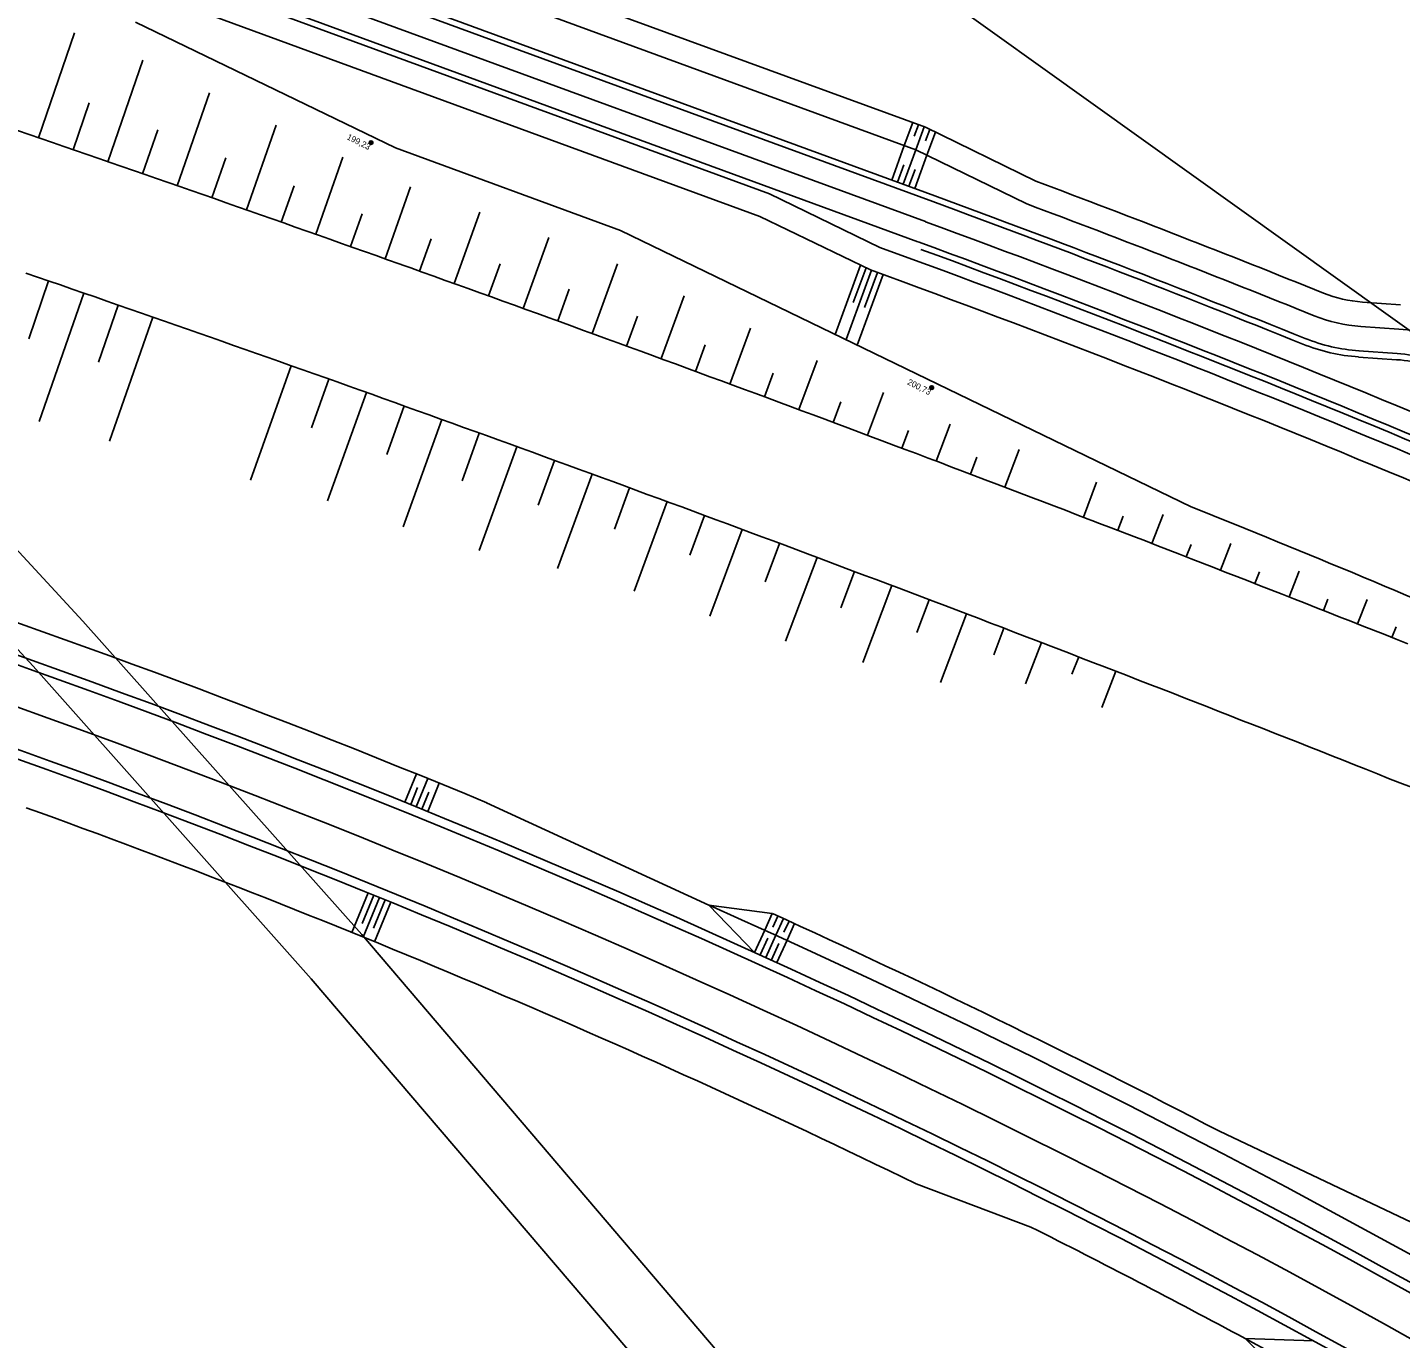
# Model space of a CAD drawing. Extents: x -551750 to -547457, y -1150683 to -1148508.
# Drawn here: x -550804.2 to -550691.9, y -1148887.3 to -1148780.1 of the extents above; entities that cross this region are included whole.
import ezdxf

# ---------------------------------------------------------------- set-up
doc = ezdxf.new("R2010")
doc.units = 0
for name, color, linetype in [('D02_ZaplUzemi20Vody', 7, 'Continuous'), ('D03_ZaplUzemi100Vody', 7, 'Continuous'), ('SO221815_VYSKOPIS', 7, 'Continuous'), ('u_ochranne_pasmo_CD', 7, 'Continuous'), ('u_trat navrh', 7, 'Continuous')]:
    doc.layers.add(name, color=color, linetype=linetype)

# ---------------------------------------------------------------- blocks, each defined once
blk = doc.blocks.new('SO221824_VYSKOPIS')
at = {"layer": 'SO221815_VYSKOPIS'}
for p, q in [((0.12, -0.09), (-0.12, 0.09)), ((0.09, 0.12), (-0.09, -0.12)), ((0.09, 0.12), (0, 0)), ((0, 0), (0.12, -0.09))]:
    blk.add_line(p, q, dxfattribs=at)
blk.add_lwpolyline([(-0.09, -0.12), (0, 0), (-0.12, 0.09)], dxfattribs=at)
blk.add_circle((0, 0), 0.15, dxfattribs=at)
for start, end in [(145.362, 235.1538), (325.362, 55.1538)]:
    blk.add_arc((0, 0), 0.15, start, end, dxfattribs=at)

msp = doc.modelspace()

# ---------------------------------------------------------------- linework, layer by layer
at = {"layer": 'D02_ZaplUzemi20Vody'}
msp.add_lwpolyline([(-550912.3, -1148731.6), (-550896.22, -1148741.39), (-550850.59, -1148781.5), (-550803.72, -1148832.3), (-550780.99, -1148857.84), (-550750.48, -1148893.58), (-550736.72, -1148911.7), (-550729.53, -1148926.8), (-550718.48, -1148952.6), (-550708.97, -1148984.08), (-550705.33, -1149008.81), (-550704.61, -1149029.83), (-550710.53, -1149089.8)], dxfattribs=at)
at = {"layer": 'D03_ZaplUzemi100Vody'}
msp.add_lwpolyline([(-550923.25, -1148724.56), (-550910.54, -1148726.8), (-550892.6, -1148737.27), (-550846.76, -1148777.57), (-550799.66, -1148828.62), (-550776.86, -1148854.24), (-550746.22, -1148890.14), (-550732.01, -1148908.84), (-550724.54, -1148924.55), (-550713.33, -1148950.72), (-550703.61, -1148982.89), (-550699.87, -1149008.32), (-550699.12, -1149030.01), (-550705.1, -1149090.59)], dxfattribs=at)
at = {"layer": 'u_ochranne_pasmo_CD'}
msp.add_lwpolyline([(-551192.01, -1148633.8), (-551157.64, -1148630.18), (-551128.55, -1148628.56), (-551093.1, -1148628.4), (-551065.82, -1148629.19), (-551032.97, -1148632.59), (-551007.77, -1148636.86), (-550975.72, -1148645.44), (-550950.32, -1148653.02), (-550933.85, -1148658.78), (-550881.95, -1148680.12), (-550842.85, -1148701.03), (-550797.65, -1148728.66), (-550648.81, -1148835.14), (-550577.65, -1148890.43), (-550478.43, -1148960.24), (-550334.99, -1149075.5), (-550242.86, -1149142.59), (-550154.88, -1149215.07), (-550068.29, -1149277.57)], dxfattribs=at)
at = {"layer": 'u_trat navrh'}
for p, q in [((-550730.77, -1148788.22), (-550845.88, -1148746.02)), ((-550731.56, -1148790.07), (-550846.57, -1148747.9)), ((-550730, -1148793.83), (-550847.6, -1148750.72)), ((-550730.17, -1148794.3), (-550847.77, -1148751.19)), ((-550730.77, -1148795.94), (-550848.38, -1148752.83)), ((-550743.53, -1148793.66), (-550849.15, -1148754.94)), ((-550731.38, -1148797.59), (-550848.98, -1148754.47)), ((-550744.31, -1148795.51), (-550849.84, -1148756.82)), ((-550795.36, -1148779.62), (-550774.11, -1148789.91)), ((-550803.29, -1148789.08), (-550800.36, -1148780.51)), ((-550797.62, -1148791.04), (-550794.76, -1148782.75)), ((-550791.95, -1148793), (-550789.3, -1148785.4)), ((-550800.45, -1148790.06), (-550799.14, -1148786.23)), ((-550732.5, -1148789.72), (-550731.81, -1148787.84)), ((-550794.78, -1148792.02), (-550793.54, -1148788.44)), ((-550786.28, -1148794.98), (-550783.85, -1148788.04)), ((-550731.68, -1148788.95), (-550731.34, -1148788.02)), ((-550731.56, -1148790.07), (-550730.87, -1148788.19)), ((-550721.74, -1148792.63), (-550730.77, -1148788.22)), ((-550730.76, -1148789.34), (-550730.42, -1148788.4)), ((-550730.66, -1148790.51), (-550729.96, -1148788.62)), ((-550755.7, -1148796.66), (-550774.11, -1148789.91)), ((-550733.53, -1148792.54), (-550732.5, -1148789.72)), ((-550732.59, -1148792.88), (-550731.56, -1148790.07)), ((-550722.53, -1148794.47), (-550731.56, -1148790.07)), ((-550789.11, -1148793.99), (-550787.97, -1148790.72)), ((-550780.62, -1148796.97), (-550778.4, -1148790.68)), ((-550733.06, -1148792.71), (-550732.55, -1148791.3)), ((-550731.65, -1148793.23), (-550730.66, -1148790.51)), ((-550732.12, -1148793.05), (-550731.62, -1148791.67)), ((-550783.45, -1148795.98), (-550782.4, -1148793)), ((-550774.96, -1148798.98), (-550772.87, -1148793.09)), ((-550743.53, -1148793.66), (-550734.49, -1148798.05)), ((-550777.79, -1148797.98), (-550776.84, -1148795.29)), ((-550769.31, -1148801), (-550767.22, -1148795.16)), ((-550744.31, -1148795.51), (-550735.27, -1148799.89)), ((-550755.7, -1148796.66), (-550709.03, -1148819.26)), ((-550772.14, -1148799.99), (-550771.19, -1148797.35)), ((-550763.67, -1148803.04), (-550761.57, -1148797.23)), ((-550731.89, -1148799), (-550734.49, -1148798.05)), ((-550766.49, -1148802.02), (-550765.55, -1148799.4)), ((-550758.02, -1148805.08), (-550755.95, -1148799.38)), ((-550736.08, -1148799.49), (-550738.16, -1148805.16)), ((-550735.17, -1148799.92), (-550737.25, -1148805.59)), ((-550735.63, -1148799.71), (-550736.67, -1148802.54)), ((-550734.23, -1148800.27), (-550736.35, -1148806.03)), ((-550734.7, -1148800.1), (-550735.75, -1148802.95)), ((-550732.58, -1148800.87), (-550735.27, -1148799.89)), ((-550802.47, -1148800.79), (-550804.09, -1148805.51)), ((-550760.84, -1148804.06), (-550759.9, -1148801.45)), ((-550799.6, -1148801.78), (-550803.23, -1148812.27)), ((-550752.39, -1148807.14), (-550750.51, -1148802.02)), ((-550695.04, -1148802.52), (-550691.92, -1148802.74)), ((-550796.77, -1148802.76), (-550798.39, -1148807.42)), ((-550755.21, -1148806.11), (-550754.32, -1148803.68)), ((-550793.94, -1148803.74), (-550797.48, -1148813.89)), ((-550746.76, -1148809.22), (-550745.07, -1148804.65)), ((-550695.18, -1148804.51), (-550692.06, -1148804.73)), ((-550749.57, -1148808.18), (-550748.77, -1148806)), ((-550695.35, -1148807.01), (-550692.24, -1148807.23)), ((-550695.32, -1148806.51), (-550692.2, -1148806.73)), ((-550782.64, -1148807.72), (-550785.95, -1148817.08)), ((-550741.13, -1148811.31), (-550739.63, -1148807.29)), ((-550779.56, -1148808.81), (-550780.98, -1148812.81)), ((-550743.94, -1148810.26), (-550743.23, -1148808.33)), ((-550776.48, -1148809.91), (-550779.65, -1148818.78)), ((-550735.51, -1148813.41), (-550734.2, -1148809.92)), ((-550773.4, -1148811.01), (-550774.82, -1148814.98)), ((-550738.32, -1148812.35), (-550737.69, -1148810.67)), ((-550770.32, -1148812.12), (-550773.48, -1148820.89)), ((-550729.89, -1148815.52), (-550728.75, -1148812.5)), ((-550767.25, -1148813.23), (-550768.66, -1148817.14)), ((-550732.7, -1148814.46), (-550732.15, -1148813.01)), ((-550764.17, -1148814.34), (-550767.25, -1148822.82)), ((-550724.28, -1148817.65), (-550723.11, -1148814.57)), ((-550761.1, -1148815.46), (-550762.43, -1148819.11)), ((-550727.08, -1148816.58), (-550726.57, -1148815.21)), ((-550758.03, -1148816.58), (-550760.86, -1148824.3)), ((-550754.96, -1148817.7), (-550756.2, -1148821.08)), ((-550717.86, -1148820.1), (-550716.77, -1148817.25)), ((-550751.89, -1148818.83), (-550754.59, -1148826.15)), ((-550748.83, -1148819.97), (-550750.03, -1148823.2)), ((-550715.05, -1148821.18), (-550714.6, -1148820.01)), ((-550712.25, -1148822.26), (-550711.33, -1148819.89)), ((-550745.76, -1148821.11), (-550748.4, -1148828.21)), ((-550742.7, -1148822.25), (-550743.87, -1148825.39)), ((-550709.44, -1148823.35), (-550709.05, -1148822.35)), ((-550706.64, -1148824.44), (-550705.79, -1148822.25)), ((-550739.63, -1148823.39), (-550742.2, -1148830.23)), ((-550736.57, -1148824.54), (-550737.69, -1148827.51)), ((-550703.84, -1148825.53), (-550703.46, -1148824.57)), ((-550701.03, -1148826.63), (-550700.21, -1148824.53)), ((-550733.51, -1148825.7), (-550735.89, -1148831.99)), ((-550730.46, -1148826.85), (-550731.47, -1148829.54)), ((-550698.23, -1148827.73), (-550697.87, -1148826.8)), ((-550695.44, -1148828.83), (-550694.65, -1148826.84)), ((-550727.4, -1148828.02), (-550729.54, -1148833.63)), ((-550724.35, -1148829.18), (-550725.18, -1148831.35)), ((-550692.64, -1148829.94), (-550692.29, -1148829.07)), ((-550721.29, -1148830.35), (-550722.6, -1148833.74)), ((-550718.24, -1148831.53), (-550718.79, -1148832.94)), ((-550715.21, -1148832.7), (-550716.35, -1148835.66)), ((-550773.33, -1148843.41), (-550772.39, -1148841.09)), ((-550772.4, -1148843.79), (-550771.46, -1148841.47)), ((-550771.47, -1148844.17), (-550770.53, -1148841.85)), ((-550772.86, -1148843.6), (-550772.3, -1148842.21)), ((-550771.94, -1148843.98), (-550771.37, -1148842.59)), ((-550766.65, -1148843.45), (-550748.47, -1148851.82)), ((-550776.34, -1148850.82), (-550777.66, -1148854.07)), ((-550775.88, -1148851.01), (-550776.82, -1148853.33)), ((-550775.42, -1148851.2), (-550776.74, -1148854.44)), ((-550774.95, -1148851.39), (-550775.9, -1148853.7)), ((-550774.49, -1148851.58), (-550775.81, -1148854.82)), ((-550743.29, -1148852.51), (-550748.47, -1148851.82)), ((-550744.74, -1148855.69), (-550748.47, -1148851.82)), ((-550743.91, -1148853.87), (-550743.29, -1148852.51)), ((-550743.25, -1148853.63), (-550742.83, -1148852.72)), ((-550743, -1148854.29), (-550742.38, -1148852.92)), ((-550743.91, -1148853.87), (-550744.74, -1148855.69)), ((-550742.34, -1148854.04), (-550741.92, -1148853.13)), ((-550742.09, -1148854.7), (-550741.47, -1148853.34)), ((-550743.66, -1148854.54), (-550744.28, -1148855.9)), ((-550743, -1148854.29), (-550743.83, -1148856.11)), ((-550742.75, -1148854.95), (-550743.37, -1148856.31)), ((-550742.09, -1148854.7), (-550742.92, -1148856.52)), ((-550706.73, -1148870.31), (-550688.66, -1148878.9)), ((-550731.54, -1148874.61), (-550722.14, -1148878.15)), ((-550699.04, -1148887.45), (-550704.63, -1148887.26)), ((-550700.96, -1148890.96), (-550704.63, -1148887.26))]:
    msp.add_line(p, q, dxfattribs=at)
for points in [[(-550805, -1148788.5), (-550804.05, -1148788.82), (-550803.1, -1148789.15), (-550802.16, -1148789.47), (-550801.21, -1148789.8), (-550800.26, -1148790.12), (-550799.32, -1148790.45), (-550798.37, -1148790.78), (-550797.42, -1148791.1), (-550796.48, -1148791.43), (-550795.53, -1148791.76), (-550794.58, -1148792.09), (-550793.64, -1148792.41), (-550792.69, -1148792.74), (-550791.75, -1148793.07), (-550790.8, -1148793.4), (-550789.86, -1148793.73), (-550788.91, -1148794.06), (-550787.96, -1148794.39), (-550787.02, -1148794.72), (-550786.07, -1148795.05), (-550785.13, -1148795.39), (-550784.19, -1148795.72), (-550783.24, -1148796.05), (-550782.3, -1148796.38), (-550781.35, -1148796.72), (-550780.41, -1148797.05), (-550779.46, -1148797.38), (-550778.52, -1148797.72), (-550777.58, -1148798.05), (-550776.63, -1148798.39), (-550775.69, -1148798.72), (-550774.75, -1148799.06), (-550773.8, -1148799.4), (-550773.43, -1148799.53), (-550772.86, -1148799.73), (-550771.92, -1148800.07), (-550770.97, -1148800.41), (-550770.03, -1148800.74), (-550769.09, -1148801.08), (-550768.15, -1148801.42), (-550767.2, -1148801.76), (-550766.26, -1148802.1), (-550765.32, -1148802.44), (-550764.38, -1148802.78), (-550763.44, -1148803.12), (-550762.49, -1148803.46), (-550761.55, -1148803.8), (-550760.61, -1148804.14), (-550759.67, -1148804.48), (-550758.73, -1148804.83), (-550757.79, -1148805.17), (-550756.85, -1148805.51), (-550755.91, -1148805.86), (-550754.97, -1148806.2), (-550754.03, -1148806.54), (-550753.09, -1148806.89), (-550752.15, -1148807.23), (-550751.21, -1148807.58), (-550750.27, -1148807.92), (-550749.33, -1148808.27), (-550748.39, -1148808.62), (-550747.45, -1148808.96), (-550746.51, -1148809.31), (-550745.57, -1148809.66), (-550744.63, -1148810), (-550743.69, -1148810.35), (-550742.75, -1148810.7), (-550741.81, -1148811.05), (-550740.88, -1148811.4), (-550739.94, -1148811.75), (-550739, -1148812.1), (-550738.06, -1148812.45), (-550737.12, -1148812.8), (-550736.19, -1148813.15), (-550735.25, -1148813.5), (-550734.31, -1148813.86), (-550733.37, -1148814.21), (-550732.44, -1148814.56), (-550731.5, -1148814.91), (-550730.56, -1148815.27), (-550729.62, -1148815.62), (-550728.69, -1148815.98), (-550727.75, -1148816.33), (-550726.82, -1148816.69), (-550725.88, -1148817.04), (-550724.94, -1148817.4), (-550724.01, -1148817.75), (-550723.07, -1148818.11), (-550722.14, -1148818.47), (-550721.2, -1148818.82), (-550720.27, -1148819.18), (-550719.33, -1148819.54), (-550718.39, -1148819.9), (-550717.46, -1148820.26), (-550717.16, -1148820.37), (-550716.53, -1148820.61), (-550715.59, -1148820.97), (-550714.66, -1148821.33), (-550713.72, -1148821.69), (-550712.79, -1148822.05), (-550711.85, -1148822.42), (-550710.92, -1148822.78), (-550709.99, -1148823.14), (-550709.05, -1148823.5), (-550708.12, -1148823.86), (-550707.19, -1148824.23), (-550706.25, -1148824.59), (-550705.32, -1148824.95), (-550704.39, -1148825.32), (-550703.45, -1148825.68), (-550702.52, -1148826.05), (-550701.59, -1148826.41), (-550700.66, -1148826.78), (-550699.72, -1148827.14), (-550698.79, -1148827.51), (-550697.86, -1148827.87), (-550696.93, -1148828.24), (-550696, -1148828.61), (-550695.07, -1148828.98), (-550694.13, -1148829.34), (-550693.2, -1148829.71), (-550692.27, -1148830.08), (-550691.34, -1148830.45)], [(-550804.32, -1148800.15), (-550803.38, -1148800.47), (-550802.43, -1148800.8), (-550801.49, -1148801.12), (-550800.55, -1148801.45), (-550799.6, -1148801.78), (-550798.66, -1148802.1), (-550797.71, -1148802.43), (-550796.77, -1148802.76), (-550795.83, -1148803.09), (-550794.88, -1148803.42), (-550793.94, -1148803.74), (-550793, -1148804.07), (-550792.06, -1148804.4), (-550791.11, -1148804.73), (-550790.17, -1148805.06), (-550789.23, -1148805.39), (-550788.29, -1148805.72), (-550787.34, -1148806.06), (-550786.4, -1148806.39), (-550785.46, -1148806.72), (-550784.52, -1148807.05), (-550783.58, -1148807.38), (-550782.63, -1148807.72), (-550781.69, -1148808.05), (-550780.75, -1148808.39), (-550779.81, -1148808.72), (-550778.87, -1148809.05), (-550777.93, -1148809.39), (-550776.99, -1148809.73), (-550776.92, -1148809.75), (-550776.05, -1148810.06), (-550775.11, -1148810.4), (-550774.17, -1148810.73), (-550773.23, -1148811.07), (-550772.29, -1148811.41), (-550771.35, -1148811.75), (-550770.41, -1148812.08), (-550769.47, -1148812.42), (-550768.53, -1148812.76), (-550767.59, -1148813.1), (-550766.65, -1148813.44), (-550765.71, -1148813.78), (-550764.77, -1148814.12), (-550763.83, -1148814.46), (-550762.89, -1148814.8), (-550761.96, -1148815.14), (-550761.02, -1148815.49), (-550760.08, -1148815.83), (-550759.14, -1148816.17), (-550758.2, -1148816.51), (-550757.27, -1148816.86), (-550756.33, -1148817.2), (-550755.39, -1148817.55), (-550754.45, -1148817.89), (-550753.52, -1148818.24), (-550752.58, -1148818.58), (-550751.64, -1148818.93), (-550750.7, -1148819.27), (-550749.77, -1148819.62), (-550748.83, -1148819.97), (-550747.89, -1148820.31), (-550746.96, -1148820.66), (-550746.02, -1148821.01), (-550745.09, -1148821.36), (-550744.15, -1148821.7), (-550743.21, -1148822.05), (-550742.28, -1148822.4), (-550741.34, -1148822.75), (-550740.41, -1148823.1), (-550739.47, -1148823.45), (-550738.54, -1148823.8), (-550737.6, -1148824.16), (-550736.67, -1148824.51), (-550735.73, -1148824.86), (-550734.8, -1148825.21), (-550733.86, -1148825.56), (-550732.93, -1148825.92), (-550732, -1148826.27), (-550731.06, -1148826.63), (-550730.13, -1148826.98), (-550729.19, -1148827.33), (-550728.26, -1148827.69), (-550727.33, -1148828.04), (-550726.39, -1148828.4), (-550725.46, -1148828.76), (-550724.53, -1148829.11), (-550723.6, -1148829.47), (-550722.66, -1148829.83), (-550721.73, -1148830.18), (-550720.8, -1148830.54), (-550720.73, -1148830.57), (-550719.87, -1148830.9), (-550718.93, -1148831.26), (-550718, -1148831.62), (-550717.07, -1148831.98), (-550716.14, -1148832.34), (-550715.21, -1148832.7), (-550714.28, -1148833.06), (-550713.34, -1148833.42), (-550712.41, -1148833.78), (-550711.48, -1148834.14), (-550710.55, -1148834.5), (-550709.62, -1148834.87), (-550708.69, -1148835.23), (-550707.76, -1148835.59), (-550706.83, -1148835.96), (-550705.9, -1148836.32), (-550704.97, -1148836.69), (-550704.04, -1148837.05), (-550703.11, -1148837.42), (-550702.18, -1148837.78), (-550701.25, -1148838.15), (-550700.32, -1148838.51), (-550699.39, -1148838.88), (-550698.47, -1148839.25), (-550697.54, -1148839.61), (-550696.61, -1148839.98), (-550695.68, -1148840.35), (-550694.75, -1148840.72), (-550693.82, -1148841.09), (-550692.9, -1148841.46), (-550691.97, -1148841.82), (-550691.04, -1148842.19)]]:
    msp.add_lwpolyline(points, dxfattribs=at)
for centre, radius, start, end in [((-551074.98, -1149734.84), 1006.25, 68.01222, 69.44873), ((-551074.98, -1149734.84), 1001.75, 68.01222, 69.86671), ((-551074.98, -1149734.84), 1002.25, 68.01222, 69.86671), ((-551074.98, -1149734.84), 1004.25, 68.01222, 69.45415), ((-551074.98, -1149734.84), 1000, 64.80614, 69.86671), ((-551074.98, -1149734.84), 998.25, 64.80614, 69.86671), ((-551074.98, -1149734.84), 996.75, 64.80614, 69.86671), ((-551074.98, -1149734.84), 997.75, 64.80614, 69.84139), ((-551074.98, -1149734.84), 994.75, 64.80614, 69.86671), ((-550694.3, -1148792.04), 10.5, 248.0122, 265.9747), ((-550694.3, -1148792.04), 12.5, 248.0122, 265.9747), ((-550693.29, -1148822.19), 17.5, 67.3044, 85.9747), ((-551056.59, -1149542.18), 756.5, 67.46341, 76.89047), ((-550694.3, -1148792.04), 15, 248.0122, 265.9747), ((-550694.3, -1148792.04), 14.5, 248.0122, 265.9747), ((-550693.29, -1148822.19), 15.5, 67.3044, 85.9747), ((-551056.59, -1149542.18), 754, 51.79075, 76.89047), ((-550693.29, -1148822.19), 15, 67.3044, 85.9747), ((-551056.59, -1149542.18), 753.25, 51.79075, 76.89047), ((-551056.59, -1149542.18), 750, 47.42068, 76.89047), ((-551074.98, -1149734.84), 986, 66.45038, 68.21372), ((-551056.59, -1149542.18), 746, 47.42068, 72.23343), ((-551056.59, -1149542.18), 746.75, 47.42068, 72.23343), ((-551056.59, -1149542.18), 742.5, 64.03774, 70.13589), ((-551056.59, -1149542.18), 756, 51.79075, 65.9476), ((-551056.59, -1149542.18), 757.5, 62.49278, 65.56866), ((-551056.59, -1149542.18), 743.5, 61.74591, 63.26712), ((-551056.59, -1149542.18), 743.5, 47.42068, 61.74591)]:
    msp.add_arc(centre, radius, start, end, dxfattribs=at)

# ---------------------------------------------------------------- block references
at = {"layer": 'u_trat navrh', "rotation": -31.851985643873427}
for p in [(-550776.1, -1148789.48), (-550730.26, -1148809.51)]:
    msp.add_blockref('SO221824_VYSKOPIS', p, dxfattribs=at)

# ---------------------------------------------------------------- texts
at = {"layer": 'u_trat navrh'}
for s, p in [('199,23', (-550778.13, -1148789.18)), ('200,73', (-550732.3, -1148809.22))]:
    msp.add_text(s, height=0.5, rotation=333.2568, dxfattribs=at).set_placement(p)

doc.saveas('drawing.dxf')
